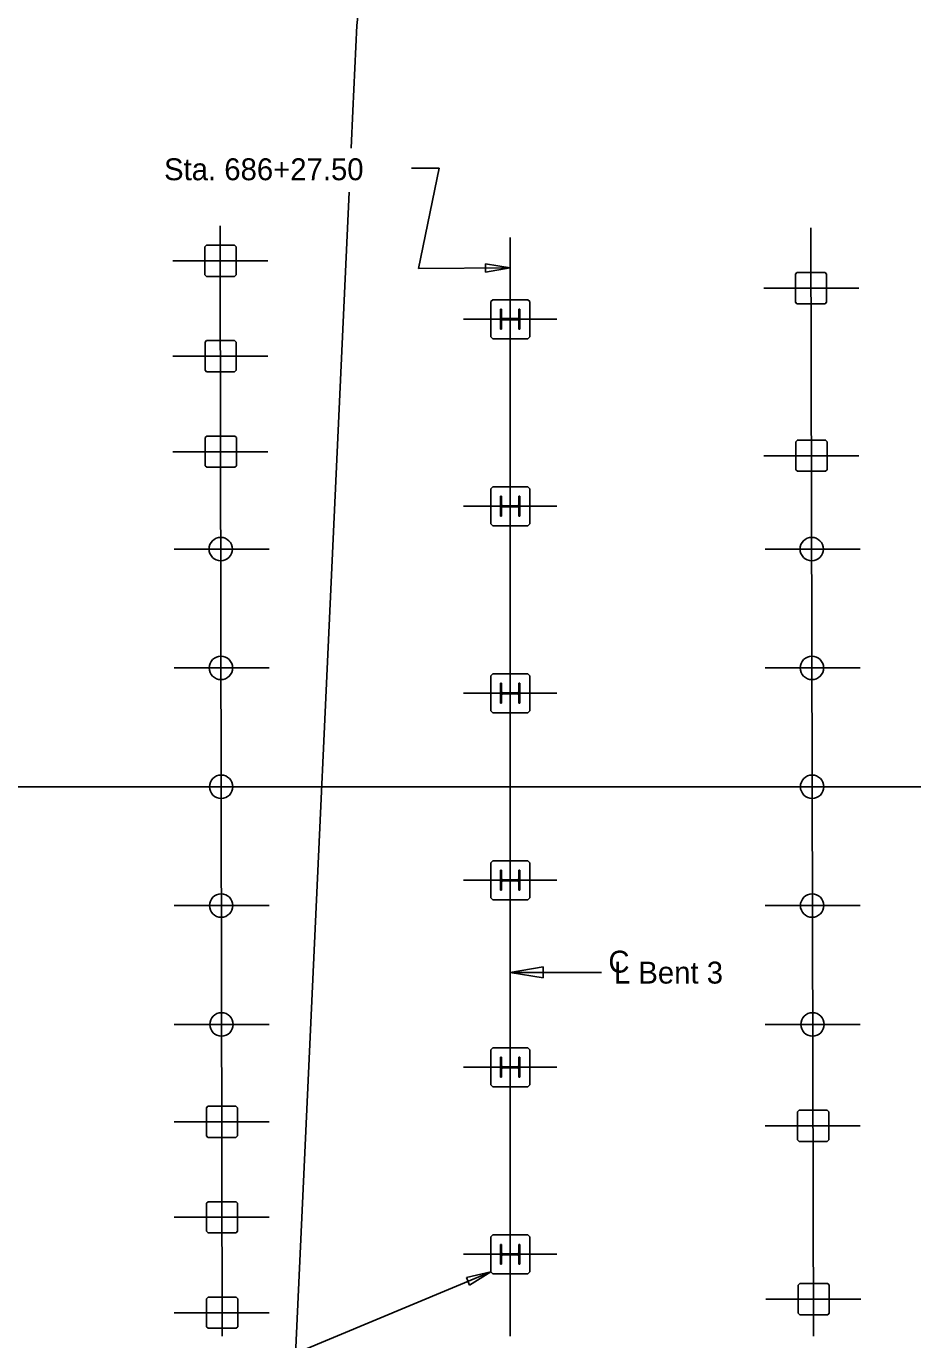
# Model space of a CAD drawing. Extents: x -463 to -191, y 251 to 416.
# Drawn here: x -317.7 to -279.7, y 310.9 to 367.1 of the extents above; entities that cross this region are included whole.
import ezdxf

# ---------------------------------------------------------------- set-up
doc = ezdxf.new("R2010")
doc.units = 0
for name, color, linetype in [('BR_AUTO DIMENSION', 7, 'Continuous'), ('BR_CONCRETE', 7, 'Continuous'), ('BR_STRUCTURAL STEEL', 7, 'Continuous'), ('BR_TEXT', 7, 'Continuous'), ('Default', 7, 'Continuous')]:
    doc.layers.add(name, color=color, linetype=linetype)

msp = doc.modelspace()

# ---------------------------------------------------------------- linework, layer by layer
at = {"layer": 'BR_AUTO DIMENSION'}
for p, q in [((-301.17, 361.045), (-299.981, 361.045)), ((-299.981, 361.045), (-300.863, 356.756)), ((-300.863, 356.756), (-296.942, 356.781)), ((-296.942, 356.781), (-297.997, 356.958)), ((-297.997, 356.958), (-297.997, 356.606)), ((-297.997, 356.606), (-296.942, 356.781)), ((-296.942, 326.643), (-295.536, 326.878)), ((-293.034, 326.643), (-296.942, 326.643)), ((-295.535, 326.409), (-296.942, 326.643)), ((-295.536, 326.878), (-295.535, 326.409)), ((-309.112, 309.113), (-297.775, 313.838)), ((-297.775, 313.838), (-298.816, 313.594)), ((-298.816, 313.594), (-298.681, 313.269)), ((-298.681, 313.269), (-297.775, 313.838))]:
    msp.add_line(p, q, dxfattribs=at)
at = {"layer": 'BR_CONCRETE'}
for p, q in [((-297.775, 355.338), (-297.692, 355.421)), ((-297.775, 355.338), (-297.775, 353.838)), ((-297.692, 355.421), (-296.192, 355.421)), ((-296.192, 355.421), (-296.109, 355.338)), ((-296.109, 355.338), (-296.109, 353.838)), ((-297.775, 353.838), (-297.692, 353.754)), ((-297.692, 353.754), (-296.192, 353.754)), ((-296.192, 353.754), (-296.109, 353.838)), ((-297.775, 347.338), (-297.692, 347.421)), ((-297.775, 347.338), (-297.775, 345.838)), ((-297.692, 347.421), (-296.192, 347.421)), ((-296.192, 347.421), (-296.109, 347.338)), ((-296.109, 347.338), (-296.109, 345.838)), ((-297.775, 345.838), (-297.692, 345.754)), ((-297.692, 345.754), (-296.192, 345.754)), ((-296.192, 345.754), (-296.109, 345.838)), ((-297.775, 339.338), (-297.692, 339.421)), ((-297.692, 339.421), (-296.192, 339.421)), ((-296.192, 339.421), (-296.109, 339.338)), ((-297.775, 339.338), (-297.775, 337.838)), ((-296.109, 339.338), (-296.109, 337.838)), ((-297.775, 337.838), (-297.692, 337.754)), ((-297.692, 337.754), (-296.192, 337.754)), ((-296.192, 337.754), (-296.109, 337.838)), ((-297.775, 331.338), (-297.692, 331.421)), ((-297.775, 331.338), (-297.775, 329.838)), ((-297.692, 331.421), (-296.192, 331.421)), ((-296.192, 331.421), (-296.109, 331.338)), ((-296.109, 331.338), (-296.109, 329.838)), ((-297.775, 329.838), (-297.692, 329.754)), ((-296.192, 329.754), (-296.109, 329.838)), ((-297.692, 329.754), (-296.192, 329.754)), ((-297.775, 323.338), (-297.692, 323.421)), ((-297.775, 323.338), (-297.775, 321.838)), ((-297.692, 323.421), (-296.192, 323.421)), ((-296.192, 323.421), (-296.109, 323.338)), ((-296.109, 323.338), (-296.109, 321.838)), ((-297.775, 321.838), (-297.692, 321.754)), ((-297.692, 321.754), (-296.192, 321.754)), ((-296.192, 321.754), (-296.109, 321.838)), ((-297.775, 315.338), (-297.692, 315.421)), ((-297.775, 315.338), (-297.775, 313.838)), ((-297.692, 315.421), (-296.192, 315.421)), ((-296.192, 315.421), (-296.109, 315.338)), ((-296.109, 315.338), (-296.109, 313.838)), ((-297.775, 313.838), (-297.692, 313.754)), ((-297.692, 313.754), (-296.192, 313.754)), ((-296.192, 313.754), (-296.109, 313.838))]:
    msp.add_line(p, q, dxfattribs=at)
for points in [[(-310.011, 356.488), (-309.944, 356.421), (-308.744, 356.421), (-308.677, 356.488), (-308.677, 357.688), (-308.744, 357.754), (-309.944, 357.754), (-310.011, 357.688)], [(-284.735, 355.315), (-284.668, 355.248), (-283.468, 355.248), (-283.401, 355.315), (-283.401, 356.515), (-283.468, 356.582), (-284.668, 356.582), (-284.735, 356.515)], [(-310.004, 352.404), (-309.937, 352.338), (-308.737, 352.338), (-308.67, 352.404), (-308.67, 353.604), (-308.737, 353.671), (-309.937, 353.671), (-310.004, 353.604)], [(-309.997, 348.321), (-309.93, 348.254), (-308.73, 348.254), (-308.663, 348.321), (-308.663, 349.521), (-308.73, 349.588), (-309.93, 349.588), (-309.997, 349.521)], [(-284.714, 348.148), (-284.647, 348.082), (-283.447, 348.082), (-283.38, 348.148), (-283.38, 349.348), (-283.447, 349.415), (-284.647, 349.415), (-284.714, 349.348)], [(-309.948, 319.654), (-309.881, 319.588), (-308.681, 319.588), (-308.615, 319.654), (-308.615, 320.854), (-308.681, 320.921), (-309.881, 320.921), (-309.948, 320.854)], [(-284.64, 319.482), (-284.573, 319.415), (-283.373, 319.415), (-283.307, 319.482), (-283.307, 320.682), (-283.373, 320.748), (-284.573, 320.748), (-284.64, 320.682)], [(-309.941, 315.571), (-309.874, 315.504), (-308.674, 315.504), (-308.608, 315.571), (-308.608, 316.771), (-308.674, 316.838), (-309.874, 316.838), (-309.941, 316.771)], [(-284.617, 312.07), (-284.551, 312.003), (-283.351, 312.003), (-283.284, 312.07), (-283.284, 313.27), (-283.351, 313.337), (-284.551, 313.337), (-284.617, 313.27)], [(-309.934, 311.488), (-309.867, 311.421), (-308.667, 311.421), (-308.601, 311.488), (-308.601, 312.688), (-308.667, 312.754), (-309.867, 312.754), (-309.934, 312.688)]]:
    msp.add_lwpolyline(points, close=True, dxfattribs=at)
for centre in [(-309.333, 344.754), (-284.038, 344.754), (-309.324, 339.671), (-284.029, 339.671), (-309.315, 334.588), (-284.021, 334.588), (-309.315, 329.504), (-284.021, 329.504), (-309.298, 324.421), (-284.003, 324.421)]:
    msp.add_circle(centre, 0.5, dxfattribs=at)
at = {"layer": 'BR_STRUCTURAL STEEL'}
for p, q in [((-297.358, 354.162), (-297.358, 355.014)), ((-297.358, 355.014), (-297.311, 355.014)), ((-297.311, 354.655), (-297.311, 355.014)), ((-296.625, 354.611), (-297.259, 354.611)), ((-296.625, 354.564), (-297.259, 354.564)), ((-296.573, 355.014), (-296.526, 355.014)), ((-296.573, 354.655), (-296.573, 355.014)), ((-296.526, 354.162), (-296.526, 355.014)), ((-297.358, 354.162), (-297.311, 354.162)), ((-297.311, 354.162), (-297.311, 354.52)), ((-296.573, 354.162), (-296.573, 354.52)), ((-296.573, 354.162), (-296.526, 354.162)), ((-297.358, 346.162), (-297.358, 347.014)), ((-297.358, 347.014), (-297.311, 347.014)), ((-297.311, 346.655), (-297.311, 347.014)), ((-296.573, 347.014), (-296.526, 347.014)), ((-296.573, 346.655), (-296.573, 347.014)), ((-296.526, 346.162), (-296.526, 347.014)), ((-297.358, 346.162), (-297.311, 346.162)), ((-297.311, 346.162), (-297.311, 346.52)), ((-296.625, 346.611), (-297.259, 346.611)), ((-296.625, 346.564), (-297.259, 346.564)), ((-296.573, 346.162), (-296.573, 346.52)), ((-296.573, 346.162), (-296.526, 346.162)), ((-297.358, 338.162), (-297.358, 339.014)), ((-297.358, 339.014), (-297.311, 339.014)), ((-297.311, 338.655), (-297.311, 339.014)), ((-296.573, 339.014), (-296.526, 339.014)), ((-296.573, 338.655), (-296.573, 339.014)), ((-296.526, 338.162), (-296.526, 339.014)), ((-297.311, 338.162), (-297.311, 338.52)), ((-296.625, 338.611), (-297.259, 338.611)), ((-296.625, 338.564), (-297.259, 338.564)), ((-296.573, 338.162), (-296.573, 338.52)), ((-297.358, 338.162), (-297.311, 338.162)), ((-296.573, 338.162), (-296.526, 338.162)), ((-297.358, 330.162), (-297.358, 331.014)), ((-297.358, 331.014), (-297.311, 331.014)), ((-297.311, 330.655), (-297.311, 331.014)), ((-296.573, 331.014), (-296.526, 331.014)), ((-296.573, 330.655), (-296.573, 331.014)), ((-296.526, 330.162), (-296.526, 331.014)), ((-297.311, 330.162), (-297.311, 330.52)), ((-296.625, 330.611), (-297.259, 330.611)), ((-296.625, 330.564), (-297.259, 330.564)), ((-296.573, 330.162), (-296.573, 330.52)), ((-297.358, 330.162), (-297.311, 330.162)), ((-296.573, 330.162), (-296.526, 330.162)), ((-297.358, 322.162), (-297.358, 323.014)), ((-297.358, 323.014), (-297.311, 323.014)), ((-297.311, 322.655), (-297.311, 323.014)), ((-297.311, 322.162), (-297.311, 322.52)), ((-296.625, 322.611), (-297.259, 322.611)), ((-296.625, 322.564), (-297.259, 322.564)), ((-296.573, 323.014), (-296.526, 323.014)), ((-296.573, 322.655), (-296.573, 323.014)), ((-296.573, 322.162), (-296.573, 322.52)), ((-296.526, 322.162), (-296.526, 323.014)), ((-297.358, 322.162), (-297.311, 322.162)), ((-296.573, 322.162), (-296.526, 322.162)), ((-297.358, 314.162), (-297.358, 315.014)), ((-297.358, 315.014), (-297.311, 315.014)), ((-297.311, 314.655), (-297.311, 315.014)), ((-296.573, 315.014), (-296.526, 315.014)), ((-296.573, 314.655), (-296.573, 315.014)), ((-296.526, 314.162), (-296.526, 315.014)), ((-297.358, 314.162), (-297.311, 314.162)), ((-297.311, 314.162), (-297.311, 314.52)), ((-296.625, 314.611), (-297.259, 314.611)), ((-296.625, 314.564), (-297.259, 314.564)), ((-296.573, 314.162), (-296.573, 314.52)), ((-296.573, 314.162), (-296.526, 314.162))]:
    msp.add_line(p, q, dxfattribs=at)
for centre, start, end in [((-297.259, 354.663), 180, 270), ((-297.259, 354.512), 90, 180), ((-296.625, 354.663), 270, 360), ((-296.625, 354.512), 360, 90), ((-297.259, 346.663), 180, 270), ((-296.625, 346.663), 270, 360), ((-297.259, 346.512), 90, 180), ((-296.625, 346.512), 360, 90), ((-297.259, 338.663), 180, 270), ((-297.259, 338.512), 90, 180), ((-296.625, 338.663), 270, 360), ((-296.625, 338.512), 360, 90), ((-297.259, 330.663), 180, 270), ((-297.259, 330.512), 90, 180), ((-296.625, 330.663), 270, 360), ((-296.625, 330.512), 360, 90), ((-297.259, 322.663), 180, 270), ((-297.259, 322.512), 90, 180), ((-296.625, 322.663), 270, 360), ((-296.625, 322.512), 360, 90), ((-297.259, 314.663), 180, 270), ((-296.625, 314.663), 270, 360), ((-297.259, 314.512), 90, 180), ((-296.625, 314.512), 360, 90)]:
    msp.add_arc(centre, 0.0521, start, end, dxfattribs=at)
at = {"layer": 'Default'}
for p, q in [((-309.354, 357.124), (-309.356, 358.588)), ((-284.082, 358.501), (-283.96, 311.088)), ((-296.942, 311.088), (-296.942, 358.088)), ((-311.378, 357.088), (-307.311, 357.088)), ((-309.276, 311.088), (-309.354, 357.088)), ((-286.083, 355.915), (-282.015, 355.915)), ((-298.942, 354.588), (-294.942, 354.588)), ((-311.378, 353.004), (-307.311, 353.004)), ((-311.378, 348.921), (-307.311, 348.921)), ((-286.083, 348.748), (-282.015, 348.748)), ((-298.942, 346.588), (-294.942, 346.588)), ((-311.322, 344.754), (-307.255, 344.754)), ((-286.027, 344.754), (-281.96, 344.754)), ((-311.322, 339.671), (-307.255, 339.671)), ((-286.027, 339.671), (-281.96, 339.671)), ((-298.942, 338.588), (-294.942, 338.588)), ((-354.498, 334.588), (-196.63, 334.588)), ((-311.322, 334.588), (-307.255, 334.588)), ((-286.027, 334.588), (-281.96, 334.588)), ((-298.942, 330.588), (-294.942, 330.588)), ((-311.322, 329.504), (-307.255, 329.504)), ((-286.027, 329.504), (-281.96, 329.504)), ((-311.322, 324.421), (-307.255, 324.421)), ((-286.027, 324.421), (-281.96, 324.421)), ((-298.942, 322.588), (-294.942, 322.588)), ((-311.32, 320.254), (-307.253, 320.254)), ((-286.025, 320.082), (-281.957, 320.082)), ((-311.32, 316.171), (-307.253, 316.171)), ((-298.942, 314.588), (-294.942, 314.588)), ((-286.004, 312.67), (-281.936, 312.67)), ((-311.32, 312.088), (-307.253, 312.088))]:
    msp.add_line(p, q, dxfattribs=at)
for points in [[(-303.675, 363.498), (-303.507, 367.154), (-303.507, 367.154), (-301.373, 386.924), (-317.47, 412.688)], [(-303.749, 361.898), (-303.675, 363.498)], [(-302.159, 303.26), (-306.131, 310.294), (-303.836, 360.025)]]:
    msp.add_lwpolyline(points, dxfattribs=at)

# ---------------------------------------------------------------- texts
at = {"layer": 'BR_TEXT'}
for s, height, p in [('Sta. 686+27.50', 0.9375, (-311.758, 360.532)), ('C', 0.938, (-292.74, 326.637)), ('L Bent 3', 0.9375, (-292.504, 326.168))]:
    msp.add_text(s, height=height, dxfattribs=at).set_placement(p)

doc.saveas('drawing.dxf')
